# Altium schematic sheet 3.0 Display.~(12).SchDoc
size A4; SheetNumber: 3; SheetTotal: 7
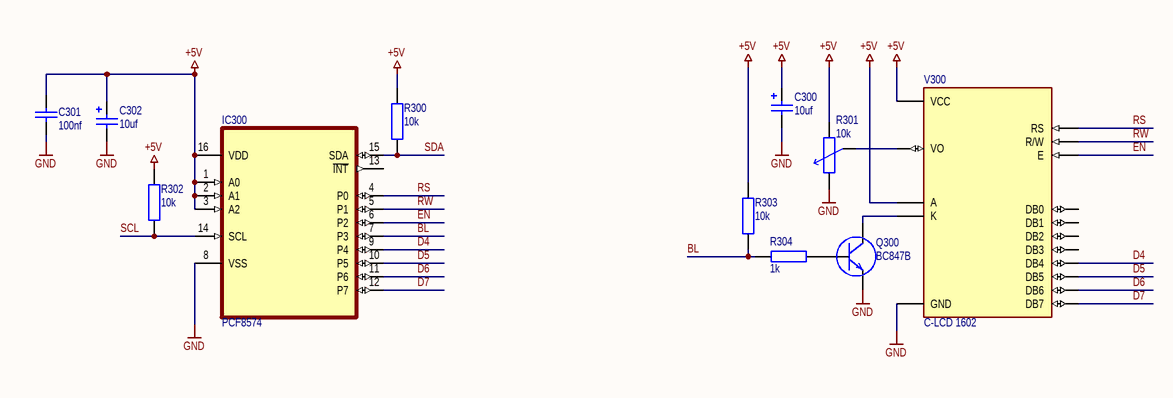
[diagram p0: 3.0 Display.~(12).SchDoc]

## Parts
C300  10uf  [C_SMD_C-TYP]
C301  100nf  [C_SMD_0805]
C302  10uf  [C_SMD_D-TYP]
IC300  PCF8574  [SO-16]
Q300  BC847B  [SOT-23]
R300  10k  [R_SMD_0805]
R301  10k  [R_THT_POT-TP-.2/.1]
R302  10k  [R_SMD_0805]
R303  10k  [R_SMD_0805]
R304  1k  [R_SMD_0805]
V300  C-LCD 1602  [V_MODULE_LCD-16X2]

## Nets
+5V: C300.1 C301.1 C302.1 IC300.1(A0) IC300.2(A1) IC300.3(A2) IC300.16(VDD) R300.2 R301.1 R302.2 R303.2 V300.2(VCC) V300.15(A)
GND: C300.2 C301.2 C302.2 IC300.8(VSS) Q300.2(E) R301.2 V300.1(GND)
BL: IC300.7(P3) R303.1 R304.1
D4: IC300.9(P4) V300.11(DB4)
D5: IC300.10(P5) V300.12(DB5)
D6: IC300.11(P6) V300.13(DB6)
D7: IC300.12(P7) V300.14(DB7)
EN: IC300.6(P2) V300.6(E)
RS: IC300.4(P0) V300.4(RS)
RW: IC300.5(P1) V300.5(R/W)
SCL: IC300.14(SCL) R302.1
SDA: IC300.15(SDA) R300.1
NetQ300_1: Q300.1(B) R304.2
NetQ300_3: Q300.3(C) V300.16(K)
NetR301_3: R301.3 V300.3(VO)

Not connected (* = marked no-connect by the designer): IC300 13(~{INT}); V300 7(DB0) 8(DB1) 9(DB2) 10(DB3)

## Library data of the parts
C300 C302 = C_SMD_ELK: SMD Elektrolytkondensator
C301 = C_SMD_KO: Kondensator SMD Universal, Keramik, Folie, usw.
IC300 = IC_PCF8574: I/O Expander
Q300 = Q_SMD_NPN: NPN Transistor
R300 R302-R304 = R_SMD_Widerstand: Widerstand SMD
R301 = R_THT_Potentiometer: Potentiometer; Set Position: 0.5
V300 = V_C-LCD-1602: LC-Display; MF: Gravitech; MP: LCD-16X2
